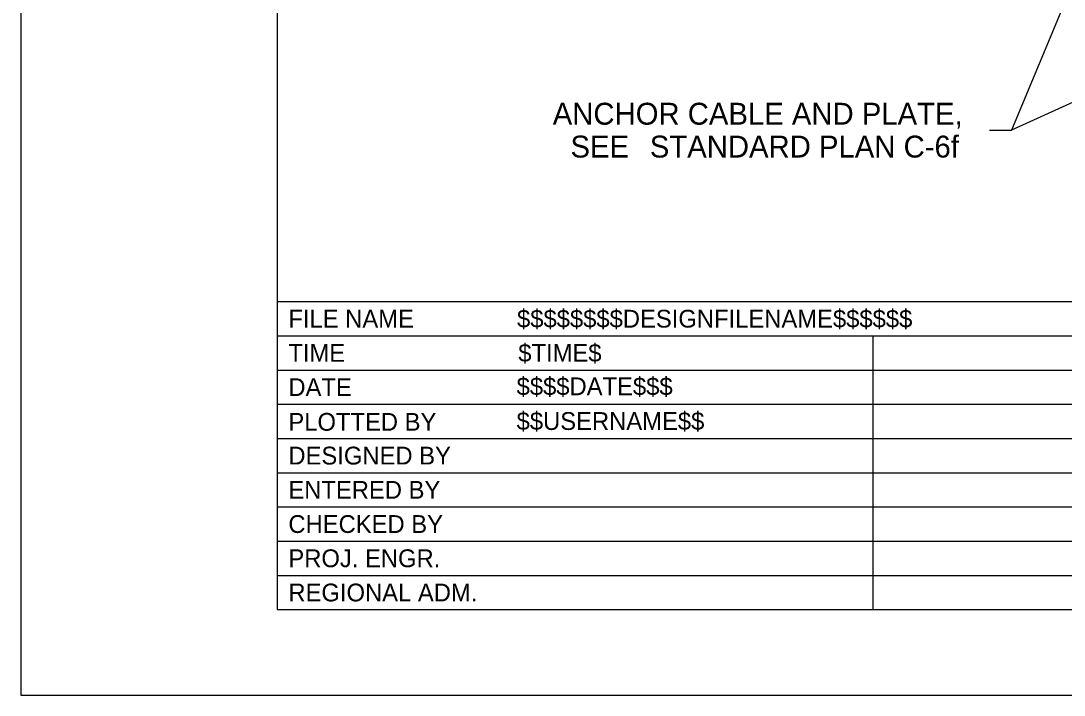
# Model space of a CAD drawing. Extents: x 1312564.2 to 1312581.5, y 1207298.4 to 1207352.6.
# Drawn here: x 1312564.478 to 1312568.294, y 1207327.221 to 1207329.685 of the extents above; entities that cross this region are included whole.
import ezdxf

# ---------------------------------------------------------------- set-up
doc = ezdxf.new("R2010")
doc.units = 0
for name, color, linetype in [('Level 1', 7, 'Continuous'), ('Level 15', 7, 'Continuous'), ('Level 2', 7, 'Continuous'), ('Level 20', 7, 'Continuous'), ('Level 36', 7, 'Continuous'), ('SH_GI_SheetTextInCells', 7, 'Continuous')]:
    doc.layers.add(name, color=color, linetype=linetype)

msp = doc.modelspace()

# ---------------------------------------------------------------- linework, layer by layer
at = {"layer": 'Level 1'}
for p, q in [((1312565.4155, 1207337.9084), (1312565.4155, 1207327.5334)), ((1312565.4155, 1207328.6593), (1312581.1655, 1207328.6593)), ((1312565.4155, 1207328.5342), (1312572.8721, 1207328.5342)), ((1312567.5945, 1207328.5342), (1312567.5945, 1207327.5334)), ((1312565.4155, 1207328.4091), (1312567.5976, 1207328.4091)), ((1312567.5976, 1207328.4091), (1312570.8621, 1207328.4091)), ((1312565.4155, 1207328.284), (1312567.5976, 1207328.284)), ((1312567.5976, 1207328.284), (1312570.8621, 1207328.284)), ((1312565.4155, 1207328.1589), (1312570.8621, 1207328.1589)), ((1312565.4155, 1207328.0338), (1312570.8621, 1207328.0338)), ((1312565.4155, 1207327.9087), (1312570.8621, 1207327.9087)), ((1312565.4155, 1207327.7836), (1312570.8621, 1207327.7836)), ((1312565.4155, 1207327.6585), (1312570.8621, 1207327.6585)), ((1312565.4155, 1207327.5334), (1312581.1655, 1207327.5334))]:
    msp.add_line(p, q, dxfattribs=at)
at = {"layer": 'Level 15'}
for p in [(1312568.3721, 1207329.9342), (1312568.9108, 1207329.6548), (1312568.021, 1207329.2858)]:
    msp.add_line(p, (1312568.101, 1207329.2858), dxfattribs=at)
at = {"layer": 'Level 2'}
msp.add_lwpolyline([(1312564.478, 1207327.2209), (1312581.478, 1207327.2209), (1312581.478, 1207338.2209), (1312564.478, 1207338.2209)], close=True, dxfattribs=at)

# ---------------------------------------------------------------- texts
at = {"layer": 'Level 20'}
for s, height, p in [('ANCHOR CABLE AND PLATE, ', 0.080077, (1312566.4235, 1207329.3058)), ('SEE ', 0.08008, (1312566.4884, 1207329.1857)), ('STANDARD PLAN C-6f', 0.080077, (1312566.7786, 1207329.1857))]:
    msp.add_text(s, height=height, dxfattribs=at).set_placement(p)
at = {"layer": 'Level 36'}
for s, height, p in [('$$$$$$$$DESIGNFILENAME$$$$$$', 0.065052, (1312566.2929, 1207328.5642)), ('$TIME$', 0.06505, (1312566.2975, 1207328.4392)), ('$$$$DATE$$$', 0.065052, (1312566.2914, 1207328.3169)), ('$$USERNAME$$', 0.065052, (1312566.2914, 1207328.1901))]:
    msp.add_text(s, height=height, dxfattribs=at).set_placement(p)
at = {"layer": 'SH_GI_SheetTextInCells'}
for s, height, p in [('FILE NAME', 0.06505, (1312565.4565, 1207328.5642)), ('TIME', 0.06505, (1312565.4565, 1207328.4391)), ('DATE', 0.06505, (1312565.4565, 1207328.314)), ('PLOTTED BY', 0.06505, (1312565.4565, 1207328.1871)), ('DESIGNED BY', 0.065052, (1312565.4565, 1207328.0638)), ('ENTERED BY', 0.06505, (1312565.4565, 1207327.9387)), ('CHECKED BY', 0.06505, (1312565.4565, 1207327.8136)), ('PROJ. ENGR.', 0.065052, (1312565.4565, 1207327.6885)), ('REGIONAL ADM.', 0.065052, (1312565.4565, 1207327.5634))]:
    msp.add_text(s, height=height, dxfattribs=at).set_placement(p)

doc.saveas('drawing.dxf')
